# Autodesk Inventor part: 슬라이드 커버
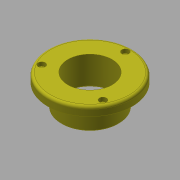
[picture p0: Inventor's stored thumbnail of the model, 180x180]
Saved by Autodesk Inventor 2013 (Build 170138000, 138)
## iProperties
Created: 2015-10
Part Number: 슬라이드 커버
Document SubType Name: Modeling
Designer: mdu
Density: 7.86 g/cm^3
Material: 강철, 연강
Mass: 635.45 g
Surface Area: 238.05 cm^2
Volume: 80.8461 cm^3
Author: mdu
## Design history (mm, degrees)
sketch "스케치1"
  geometry: C1 r 47.5 at (0, 0); C2 r 32.5 at (0, 0); 1 further point
  constraints: 2 centre point, 2 coincident
  dimensions: "d33" = 95 diameter of C1; "d35" = 65 diameter of C2
extrude "돌출1" new body sketch "스케치1" distance "d0" = 10; taper "d1" = 0 deg
extrude "돌출2" join sketch "스케치1" distance "d2" = 25; taper "d3" = 0 deg
hole "구멍1" diameter "d6" = 50; stored, may be unused: countersink angle "d10" = 90 deg, drill point angle "d12" = 118 deg; dims "d4" = 10, "d5" = 10, "d7" = 6, "d8" = 4, "d9" = 2, "d11" = 8
sketch "스케치2" dims "d36" = 80
  geometry: 4 further points
  constraints: 2 coincident, 2 vertical alignment, 2 other
hole "구멍2" sketch "스케치2" at (0, 40) diameter "d13" = 4.5; stored, may be unused: countersink angle "d17" = 90 deg, drill point angle "d19" = 118 deg; dims "d14" = 6, "d15" = 8, "d16" = 4.4, "d18" = 8
fillet "모깎기1" dims "d23" = 3
chamfer "모따기1" distance "d24" = 1; stored, may be unused: second distance "d25" = 2, angle "d26" = 45 deg
sketch "스케치3"
  geometry: C1 r 25 at (0, 0); C2 r 30 at (0, 0); C3 r 26 at (0, 0) reference; 1 further point
  constraints: 2 centre point, 2 coincident
  dimensions: "d27" = 60 diameter of C2
extrude "돌출3" cut sketch "스케치3" distance "d28" = 3; taper "d29" = 0 deg
chamfer "모따기2" distance "d30" = 1; stored, may be unused: second distance "d31" = 2, angle "d32" = 45 deg
node "솔리드1"
pattern_circular "원형 패턴1" dims angle "d21" = 360 deg
